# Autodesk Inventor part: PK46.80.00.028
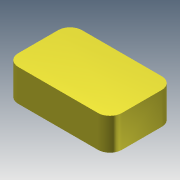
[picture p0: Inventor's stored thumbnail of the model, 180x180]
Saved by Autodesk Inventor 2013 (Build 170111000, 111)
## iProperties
Created: 2005-05
Part Number: PK46.80.00.028
Material: Steel, Mild
Document SubType Name: Modeling
Designer: salex
Manufacturer: Standard
Standards Organization: Custom
Density: 7.86 g/cm^3
Mass: 3209.04 g
Surface Area: 361.836 cm^2
Volume: 408.275 cm^3
Author: salex
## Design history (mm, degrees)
sketch "Эскиз1"
  geometry: L1 (0, 0)-(130, 0); L2 (130, 0)-(130, 80); L3 (130, 80)-(0, 80); L4 (0, 80)-(0, 0)
  constraints: 8 end point, 2 parallel, 1 horizontal, 1 perpendicular, 1 other
  dimensions: "d0" = 80 distance of L3.end L1.start; "d1" = 130 distance of L1.start L1.end
extrude "Выдавливание1" new body sketch "Эскиз1" distance "d2" = 40; taper "d3" = 0 deg
fillet "Сопряжение1" dims "d4" = 15
body "Solid1"
